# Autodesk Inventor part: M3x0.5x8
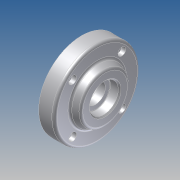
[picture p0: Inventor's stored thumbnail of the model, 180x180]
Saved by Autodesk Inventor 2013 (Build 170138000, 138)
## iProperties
Company: 한국ATC센터
Created: 2009-02
Part Number: M3x0.5x8
Document SubType Name: Modeling
Designer: KYOUNG IL JANG
Density: 2.71 g/cm^3
Mass: 114.339 g
Surface Area: 117.889 cm^2
Volume: 42.1916 cm^3
Material: 알루미늄-6061
Vendor: CBT Solutions
Author: KYOUNG IL JANG
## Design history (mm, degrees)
sketch "스케치1"
  geometry: L1 (-11.5, 0)-(11.5, 0); L2 (11.5, 0)-(11.5, 22.5); L3 (11.5, 22.5)-(6.5, 22.5); L4 (6.5, 22.5)-(6.5, 32.5); L5 (6.5, 32.5)-(-5.5, 32.5); L6 (-5.5, 32.5)-(-5.5, 21); L7 (-5.5, 21)-(-11.5, 18.202); L8 (-11.5, 18.202)-(-11.5, 0); 2 further points
  constraints: 16 end point, 3 parallel, 3 perpendicular, 1 coincident, 1 horizontal, 1 midpoint
  dimensions: "d0" = 23 distance of L1.start L1.end; "d1" = 65 diameter of L5 L1; "d2" = 45 diameter of L3 L1; "d3" = 42 diameter of L6.end L1; "d4" = 115 deg angle of L7 L6; "d5" = 12 distance of L4.end L5.end; "d6" = 5 distance of L2.end L3.end
revolve "회전1" sketch "스케치1" stored, may be unused: angle "d7" = 90 deg
sketch "스케치2"
  geometry: L1 (0, 0)-(32.5, 0); L2 (0, 0)-(18.738, 18.738); 1 further point
  constraints: 4 end point, 1 horizontal, 1 horizontal alignment, 1 other
  dimensions: "d8" = 45 deg angle of L1 L2; "d9" = 26.5 distance of L1.start L2.end
hole "구멍1" sketch "스케치2" at (18.738, 18.738) diameter "d10" = 3.4; stored, may be unused: countersink angle "d14" = 90 deg, drill point angle "d16" = 118 deg; dims "d11" = 6, "d12" = 6, "d13" = 3.3, "d15" = 8
fillet "모깎기1" dims "d20" = 2
hole "구멍2" diameter "d23" = 15; stored, may be unused: countersink angle "d27" = 90 deg, drill point angle "d29" = 118 deg; dims "d21" = 10, "d22" = 10, "d24" = 6, "d25" = 32, "d26" = 10, "d28" = 8
hole "구멍3" diameter "d32" = 22; stored, may be unused: countersink angle "d36" = 90 deg, drill point angle "d38" = 0 deg; dims "d30" = 10, "d31" = 10, "d33" = 6, "d34" = 32, "d35" = 10, "d37" = 7.3
chamfer "모따기1" distance "d39" = 1; stored, may be unused: second distance "d40" = 2, angle "d41" = 45 deg
fillet "모깎기2" dims "d42" = 0.3
node "솔리드1"
pattern_circular "원형 패턴1" dims angle "d18" = 360 deg
